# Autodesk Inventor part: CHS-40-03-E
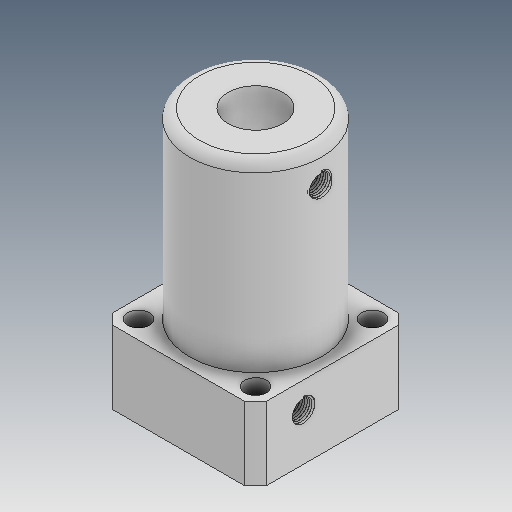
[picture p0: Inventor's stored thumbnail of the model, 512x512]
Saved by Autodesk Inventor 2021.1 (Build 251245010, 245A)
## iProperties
Created: 2019-04
Part Number: CHS-40-03-E
Material: Ogólny
Document SubType Name: Modeling
Designer: user
Density: 1 g/cm^3
Appearance: Domyślna
Author: user
Revision Number: ÈÎºÎ
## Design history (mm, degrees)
feature "ÊäÈë1"
node "Bryła1"
